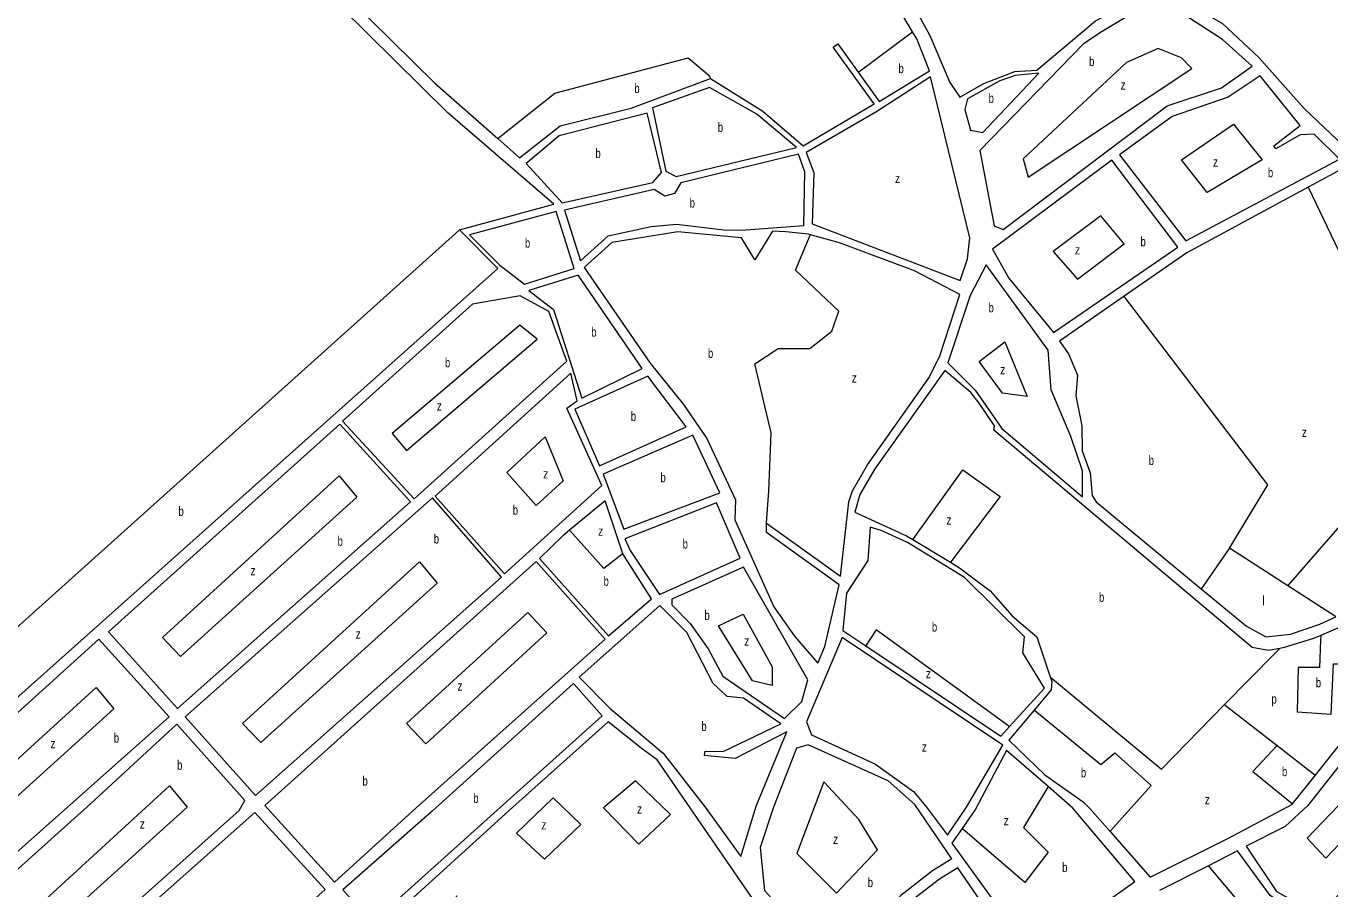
# Model space of a CAD drawing. Extents: x 639657 to 671642, y 222838 to 252123.
# Drawn here: x 645919 to 647301, y 229914 to 230829 of the extents above; entities that cross this region are included whole.
import ezdxf

# ---------------------------------------------------------------- set-up
doc = ezdxf.new("R2010")
doc.units = 0
doc.header["$LTSCALE"] = 4
doc.layers.add('1', color=7, linetype='Continuous', lineweight=13)
doc.layers.add('21', color=7, linetype='Continuous', lineweight=13)
doc.layers.add('7', color=7, linetype='Continuous')

msp = doc.modelspace()

# ---------------------------------------------------------------- linework, layer by layer
at = {"layer": '1'}
for p, q in [((646352.11, 230768.6), (646418.897, 230709.804)), ((646532.759, 230325.888), (646495.093, 230294.464)), ((646925.51, 229998.75), (646911.318, 229978.511)), ((647046.81, 229999.51), (647068.059, 229975.341))]:
    msp.add_line(p, q, dxfattribs=at)
for points in [[(646484.8, 231076.85), (646487.37, 231097.94), (646593.98, 231193.6), (646489.25, 231341.24), (646476.71, 231348.42), (646461.49, 231345.04), (646106.5, 231111.23), (646232.02, 230887.3), (646260.731, 230858.921), (646352.11, 230768.6)], [(646378.26, 230612.84), (646478.3, 230640.08), (646366.2, 230736.72), (646223.74, 230877.97), (646098.63, 231103.63), (645307.38, 230579.87)], [(646755.512, 231015.865), (646765.29, 231007.31), (646777.26, 230992.6), (646814.88, 230930.44), (646837.21, 230891.55), (646839.54, 230895.23), (646841.31, 230889.88), (646838.96, 230888.78), (646876.87, 230819.1), (646898.24, 230769.24), (646908.72, 230753.45), (646934.13, 230768.11), (646967.3, 230780.91), (646990.49, 230782.22), (647052.67, 230834.45), (647091.34, 230854.62), (647119.65, 230859.64), (647086.48, 230927.22), (647043.96, 230965.68), (647001.04, 231021.76), (646997.262, 231027.37)], [(646801.076, 230780.211), (646823.48, 230748.92), (646876.84, 230781.49), (646863.16, 230815.31), (646858.611, 230823.014), (646759.357, 230991.083)], [(646644.46, 230773.52), (646700.05, 230738.84), (646742.76, 230702.1), (646817.92, 230746.5), (646774.52, 230806.45), (646779.64, 230810.15), (646801.076, 230780.211)], [(646418.897, 230709.804), (646442.12, 230689.36), (646484.94, 230723.11), (646560.37, 230741.93), (646644.46, 230773.52)], [(647392.16, 230197.41), (647423.87, 230225.68), (647410.6, 230241.45), (647417.04, 230262.79), (647448.84, 230323.95), (647467.17, 230338.11), (647428.13, 230393.81), (647420.44, 230410.49), (647414.62, 230453.21), (647421.06, 230494.54), (647419.31, 230518.17), (647414.97, 230542.2), (647405.09, 230562.73), (647318.78, 230680.06), (647278.148, 230658.148)], [(647278.148, 230658.148), (647149.37, 230588.7), (647082.994, 230542.613)], [(645699.51, 230001.83), (645730.15, 229955.63), (645778.98, 230000.9), (646419.09, 230572), (646378.26, 230612.84)], [(646750.393, 230607.657), (646748.27, 230608.23), (646724.18, 230611), (646710.21, 230611.71), (646691.41, 230581.22), (646677.2, 230604.5), (646609.89, 230610.69), (646539.96, 230599.66), (646510.6, 230572.93), (646580.42, 230471.55), (646615.69, 230427.85), (646640.56, 230391.78), (646670.9, 230326.76), (646670.26, 230305.69), (646711.62, 230213.26), (646733.64, 230182.32)], [(646703.81, 230301.95), (646782.17, 230246), (646791.23, 230324.76), (646795.19, 230336.19), (646810.79, 230363.86), (646876.2, 230456.51), (646887.56, 230479.41), (646909, 230544.54), (646860.61, 230569.62), (646781.24, 230599.33), (646750.393, 230607.657)], [(647082.994, 230542.613), (647014.58, 230495.11), (647023.96, 230481.66), (647033.44, 230458.98), (647031.73, 230437.04), (647038.3, 230405.08), (647038.37, 230378.64), (647046.99, 230355.52), (647049.17, 230331.47), (647053.33, 230324.63), (647164.812, 230232.354)], [(647247.995, 230169.347), (647236.07, 230167.23), (647218.86, 230170.28), (646944.9, 230400.47), (646945.71, 230405.21), (646929.34, 230429.11), (646920.41, 230440.63), (646892.88, 230463.99), (646818.57, 230359.64), (646802.74, 230332.61), (646797.36, 230313.64), (646852.4, 230288.63), (646859.069, 230284.602), (646898.821, 230260.596)], [(646495.093, 230294.464), (646488.04, 230288.58), (646463.16, 230264.69), (646536.42, 230182.69), (646581.98, 230221.83), (646551.4, 230269.67), (646532.759, 230325.888)], [(646733.64, 230182.32), (646758.22, 230153.56), (646765.77, 230171.26), (646780.98, 230236.75), (646703.7, 230292.27), (646703.81, 230301.95)], [(646825.49, 230294.37), (646813.85, 230297.91), (646811.21, 230262.63), (646788.59, 230228.01), (646784.71, 230188.43), (646809.117, 230172.105)], [(646961.395, 230086.557), (646998.46, 230127.2), (646975.73, 230164.58), (646977.48, 230181.58), (646913.66, 230244.55), (646853.34, 230281.55), (646825.49, 230294.37)], [(646898.821, 230260.596), (646908.4, 230254.81), (646941.1, 230230.43), (646964.15, 230203.8), (646990.37, 230181.71), (647004.712, 230139.007), (647006.34, 230134.16)], [(647164.812, 230232.354), (647212.61, 230192.79), (647233.13, 230181.6), (647259.53, 230184.45), (647290.57, 230195.08), (647307.563, 230202.823)], [(647285.839, 230035.07), (647319.5, 230077.38), (647378.34, 230183.08), (647374.59, 230192.29), (647352.99, 230204.11), (647337.74, 230203.09), (647327.424, 230198.624), (647291.418, 230183.037)], [(647291.418, 230183.037), (647283.85, 230179.76), (647252.8, 230170.2), (647247.995, 230169.347)], [(646809.117, 230172.105), (646952.16, 230076.43), (646961.395, 230086.557)], [(647006.34, 230134.16), (647005.78, 230125.34), (646987.763, 230103.978)], [(647447.177, 230043.946), (647362.14, 230129.83), (647333.05, 230075.8), (647330.33, 230069.54), (647277.75, 230002.84)], [(646987.763, 230103.978), (646960.8, 230072.01), (646998.78, 230035.21), (647039.46, 230006.82), (647046.81, 229999.51)], [(646572.48, 230062.48), (646536.09, 230091.35), (646435.02, 230001.02)], [(646767.742, 229817.124), (646688.86, 229904.36), (646588.07, 230051.04), (646572.48, 230062.48)], [(646900.437, 229946.163), (646861, 230003.75), (646832.78, 230028.8), (646747.95, 230067.06), (646735.53, 230063.49), (646711.38, 230001.02)], [(647002.498, 230022.756), (646958.33, 230061.24), (646925.51, 229998.75)], [(647277.75, 230002.84), (647253.93, 229980.38), (647212.54, 229959.77), (647244.66, 229911.71), (647289.1, 229886.83), (647447.177, 230043.946)], [(647192.85, 229967.84), (647261.4, 230004.35), (647261.555, 230004.545), (647285.839, 230035.07)], [(646911.318, 229978.511), (646900.35, 229962.87), (646956.79, 229884.9), (646973.19, 229839.18), (646997.39, 229844.71), (647068.72, 229903.83), (647094.45, 229922.27), (647028.49, 230000.11), (647002.498, 230022.756)], [(646435.02, 230001.02), (646291.47, 229870.62), (646327.34, 229831.43), (646345.78, 229848.27), (646375.943, 229907.208)], [(646711.38, 230001.02), (646697.05, 229958.42), (646701.85, 229912.51), (646774.922, 229832.487)], [(647068.059, 229975.341), (647110.72, 229926.82), (647192.85, 229967.84)], [(647301.117, 229864.83), (647237.84, 229907.31), (647203.16, 229954.68), (647172.346, 229938.966), (647120.61, 229912.58)], [(646900.437, 229946.163), (646879.78, 229933.446), (646846.318, 229907.407), (646819.052, 229881.368), (646774.922, 229832.487)], [(646906.824, 229936.837), (646887.217, 229924.766), (646853.755, 229898.727), (646826.489, 229872.688), (646791.787, 229834.25), (646783.458, 229823.139)], [(646783.458, 229823.139), (646836.1, 229765.49), (646946.22, 229845.63), (646951.17, 229858.82), (646943.27, 229883.62), (646906.824, 229936.837)]]:
    msp.add_lwpolyline(points, dxfattribs=at)
for points in [[(647322.92, 230694.94), (647450.69, 230760.95), (647421.47, 230802.35), (647412.14, 230810.2), (647318.91, 230849.65), (647281.51, 230871.62), (647267.87, 230882.01), (647158.45, 231008.56), (647146.93, 231001.13), (647131.56, 230971.31), (647093.24, 230938.68), (647126.72, 230861.64), (647143.54, 230855.15), (647149.56, 230855.22), (647154.38, 230866.44), (647145.25, 230896.22), (647163.49, 230898.99), (647171, 230879.29), (647158.16, 230854.44), (647164.06, 230845.26), (647187.41, 230831.53), (647225.81, 230795.82), (647274.08, 230741.51)], [(647186.2, 230763.39), (647218.82, 230786.29), (647187.37, 230814.77), (647142.59, 230843.75), (647124.08, 230847.22), (647107.33, 230846.4), (647084.64, 230838), (647059.66, 230823.34), (647040.04, 230810.03), (646930.16, 230697.14), (646945.4, 230617.34), (646954.68, 230613.35), (647128.82, 230744.53)], [(646933.18, 230716.08), (646992.45, 230779.02), (646967.35, 230776.4), (646951.29, 230771.08), (646917.12, 230751.81), (646914.02, 230740.6), (646920.26, 230718.75)], [(647148.38, 230601.37), (647311.39, 230687.94), (647284.68, 230714.53), (647269.65, 230713.52), (647244.03, 230698.85), (647241.63, 230702.05), (647269.76, 230723.62), (647227.31, 230776.27), (647193.17, 230753.57), (647134.1, 230732.97), (647078.23, 230692.64)], [(646643.49, 230763.84), (646583.14, 230742.16), (646597.17, 230675.04), (646607.97, 230669.56), (646735.69, 230700.09), (646693.64, 230735.55)], [(646919.54, 230604.61), (646877.77, 230775.05), (646819.73, 230737.7), (646746.06, 230695.04), (646754.02, 230673.84), (646752.24, 230619.45), (646909.28, 230559.37), (646916.98, 230582.23)], [(646583.33, 230663.29), (646592.67, 230673.7), (646577.39, 230736.73), (646483.98, 230712.57), (646449.06, 230683.2), (646487.1, 230641.46)], [(646744.34, 230674.6), (646737.7, 230693.23), (646613.2, 230662.73), (646606.23, 230651.49), (646596.16, 230648.59), (646584.92, 230655.78), (646489.54, 230633.96), (646506.66, 230579.98), (646535.81, 230606.71), (646581.47, 230616.42), (646608.51, 230619.06), (646658.63, 230613.12), (646677.33, 230612.67), (646743.45, 230617.64)], [(647008.25, 230504.29), (647140.07, 230594.62), (647070.13, 230686.97), (646943.3, 230592.6), (646960.81, 230561.83)], [(646499.87, 230571.96), (646480.75, 230632.58), (646389.06, 230607.58), (646420.98, 230575.67), (646447.19, 230555.52)], [(647002.44, 230485.53), (646936.6, 230575.98), (646919.76, 230543.36), (646896.02, 230471.97), (646925.11, 230443.04), (646953.25, 230402.49), (647038.88, 230329.86), (647038.8, 230357.37), (647026.6, 230393.78), (647005.67, 230443.43)], [(646572.11, 230465.88), (646504.03, 230564.91), (646451.99, 230548.69), (646477.99, 230528.54), (646508.2, 230434.5)], [(646330.37, 230327.82), (646492.1, 230473.88), (646473.06, 230526.55), (646442.6, 230543.01), (646392.2, 230534.11), (646254.3, 230410.21)], [(646503.29, 230431.87), (646496.32, 230461.03), (646352.46, 230330.83), (646426.16, 230248.41), (646529.16, 230341.87), (646492.2, 230423.8)], [(646618.74, 230404.03), (646578.2, 230457.99), (646500.59, 230422.81), (646526.79, 230362.69)], [(646326.53, 230324.55), (646251.54, 230406.96), (646006.38, 230186.79), (646079.2, 230105.64)], [(646654.27, 230334.33), (646625.7, 230395.29), (646530.53, 230354.13), (646552.42, 230295.68)], [(646422.98, 230244.72), (646349.69, 230328.87), (646087.67, 230096.92), (646162.24, 230013.21)], [(646675.84, 230264.91), (646650.95, 230323.76), (646553.6, 230285.59), (646559.32, 230272.97), (646590.31, 230226.43)], [(646172.1, 230002.84), (646245.75, 229921.47), (646332.38, 230000.17), (646532.81, 230179), (646459.54, 230261.43)], [(646747.66, 230136.04), (646679.6, 230255.28), (646603.47, 230221.41), (646603.32, 230215.39), (646623.08, 230195.82), (646642.05, 230168.93), (646657.61, 230139.86), (646722.96, 230094.96), (646741.46, 230112.98)], [(646638.7, 230001.02), (646676.57, 229948.64), (646692.76, 230001.93), (646725.47, 230080.8), (646670.55, 230052.73), (646638.08, 230055.63), (646638.89, 230060.36), (646658.01, 230059.91), (646718.93, 230089.33), (646679.55, 230116.44), (646662.13, 230118.2), (646647.37, 230132.23), (646619.52, 230186.32), (646590.87, 230214.83), (646505.3, 230138.74), (646538.31, 230105.12), (646594.44, 230058.41)], [(645797.39, 229999.45), (645737.19, 229945), (645803.46, 229859.66), (646070.49, 230096.75), (645995.93, 230179.16)], [(646872.42, 230002.31), (646895.92, 229971.18), (646915.97, 230001.02), (646954.41, 230066.79), (646783.93, 230180.68), (646746.19, 230091.54), (646751.49, 230077.62), (646819.27, 230046.72), (646859.75, 230017.47)], [(646349.22, 229996.66), (646254.7, 229913.23), (646285.76, 229878.91), (646529.58, 230097.73), (646499.35, 230132.24)], [(645986.99, 230004.65), (645813.09, 229848.86), (645886.82, 229767.29), (646144.6, 229997.51), (646150.69, 230007.94), (646078.52, 230088.87)], [(646161.41, 229995.34), (645895.33, 229759.04), (645969.95, 229675.77), (646235.99, 229913.58)]]:
    msp.add_lwpolyline(points, close=True, dxfattribs=at)
at = {"layer": '21'}
for points in [[(646801.076, 230780.211), (646801.576, 230780.583), (646858.611, 230823.014)], [(646418.897, 230709.804), (646419.397, 230710.202), (646479.466, 230758.007), (646620.753, 230795.205), (646643.062, 230776.606), (646644.233, 230774.02), (646644.46, 230773.52)], [(647278.148, 230658.148), (647278.387, 230657.648), (647309.839, 230591.855), (647354.456, 230541.017), (647316.035, 230514.978), (647339.583, 230479.02), (647373.046, 230507.539), (647395.354, 230472.82), (647358.174, 230445.542), (647397.833, 230400.904), (647375.525, 230381.065), (647405.269, 230342.627), (647386.679, 230327.747), (647371.807, 230315.348), (647360.652, 230304.188), (647387.918, 230269.47), (647373.046, 230255.831), (647325.95, 230315.348), (647257.032, 230236.183), (647256.597, 230235.683)], [(646378.26, 230612.84), (646377.76, 230612.391), (645768.61, 230065.789), (645768.11, 230065.34)], [(646703.81, 230301.95), (646703.846, 230302.45), (646706.27, 230335.807), (646708.749, 230397.804), (646691.398, 230470.961), (646716.185, 230487.08), (646749.648, 230487.08), (646773.196, 230505.679), (646780.632, 230526.758), (646734.775, 230570.156), (646750.185, 230607.157), (646750.393, 230607.657)], [(647194.578, 230275.669), (647235.477, 230342.626), (647083.375, 230542.113), (647082.994, 230542.613)], [(646859.069, 230284.602), (646859.426, 230285.103), (646912.004, 230358.745), (646951.663, 230330.227), (646899.199, 230261.095), (646898.821, 230260.596)], [(646551.4, 230269.67), (646550.9, 230269.275), (646531.52, 230253.971), (646495.543, 230293.964), (646495.093, 230294.464)], [(647194.578, 230275.669), (647194.234, 230275.169), (647165.156, 230232.854), (647164.812, 230232.354)], [(647307.563, 230202.823), (647307.063, 230203.145), (647256.597, 230235.683), (647194.578, 230275.669)], [(647291.418, 230183.037), (647291.21, 230178.036), (647290.009, 230149.195), (647267.701, 230149.195), (647266.461, 230102.078), (647302.403, 230099.598), (647304.881, 230152.915), (647325.951, 230152.915), (647327.408, 230198.124), (647327.424, 230198.624)], [(646961.395, 230086.557), (646960.895, 230086.92), (646820.291, 230188.873), (646809.45, 230172.605), (646809.117, 230172.105)], [(647189.585, 230109.666), (647243.101, 230164.347), (647247.995, 230169.347)], [(647004.712, 230139.007), (647005.212, 230138.593), (647122.695, 230041.321), (647189.585, 230109.666)], [(646987.763, 230103.978), (646988.263, 230103.569), (647058.248, 230046.28), (647073.121, 230058.68), (647111.541, 230023.961), (647068.506, 229975.841), (647068.059, 229975.341)], [(647189.585, 230109.666), (647190.085, 230109.279), (647245.342, 230066.455)], [(647245.342, 230066.455), (647244.872, 230065.955), (647219.365, 230038.841), (647261.055, 230004.951), (647261.555, 230004.545)], [(647245.342, 230066.455), (647285.339, 230035.457), (647285.839, 230035.07)], [(647002.498, 230022.756), (647002.198, 230022.256), (646976.451, 229979.323), (647002.477, 229953.285), (646977.69, 229921.046), (646911.818, 229978.078), (646911.318, 229978.511)], [(647301.117, 229864.83), (647300.675, 229864.33), (647274.004, 229834.166), (647260.419, 229840.439), (647238.474, 229823.711), (647200.854, 229867.622), (647223.844, 229878.077), (647172.77, 229938.465), (647172.346, 229938.966)]]:
    msp.add_lwpolyline(points, dxfattribs=at)
for points in [[(646976.091, 230688.235), (646981.408, 230668.731), (647154.918, 230784.046), (647143.764, 230795.205), (647118.977, 230805.125), (647085.514, 230790.245)], [(647199.03, 230725.161), (647229.28, 230687.33), (647171.03, 230652.612), (647143.764, 230687.33)], [(647007.926, 230590.053), (647033.461, 230560.856), (647083.035, 230598.054), (647058.248, 230627.813)], [(646307.03, 230396.985), (646322.068, 230379.205), (646460.877, 230496.999), (646442.286, 230511.879)], [(646956.666, 230494.336), (646980.169, 230436.242), (646954.142, 230439.962), (646929.355, 230473.441)], [(646469.232, 230393.538), (646488.142, 230346.967), (646459.637, 230320.928), (646428.653, 230355.646)], [(646250.754, 230352.206), (646269.523, 230329.671), (646082.537, 230160.582), (646063.358, 230180.968)], [(646335.857, 230261.066), (646354.626, 230238.531), (646167.64, 230069.442), (646148.461, 230089.828)], [(646450.914, 230207.184), (646470.894, 230185.765), (646342.641, 230068.242), (646322.264, 230089.828)], [(646652.855, 230193.221), (646679.004, 230205.613), (646709.988, 230149.816), (646709.988, 230129.977), (646688.919, 230134.937)], [(645993.048, 230127.953), (646011.817, 230105.418), (645824.831, 229936.329), (645805.652, 229956.715)], [(647360.544, 230054.959), (647380.595, 230034.9), (647296.994, 229947.079), (647277.139, 229967.989)], [(646070.959, 230023.621), (646089.728, 230001.086), (645902.742, 229831.997), (645883.563, 229852.383)], [(646565.048, 230028.963), (646531.009, 230000.4), (646568.629, 229961.717), (646602.069, 229993.081)], [(646764.483, 230027.996), (646736.015, 229952.045), (646778.153, 229909.887), (646821.53, 229955.765), (646801.701, 229988.003)], [(646438.856, 229973.319), (646468.309, 229946.034), (646506.974, 229982.626), (646477.714, 230010.855)]]:
    msp.add_lwpolyline(points, close=True, dxfattribs=at)

# ---------------------------------------------------------------- texts
at = {"layer": '7'}
for s, width, p in [('b', 0.75, (646843.838, 230779.086)), ('b', 0.75, (647045.855, 230786.525)), ('b', 0.75, (646563.742, 230758.007)), ('z', 0.8, (647079.317, 230761.727)), ('b', 0.75, (646939.378, 230747.55)), ('b', 0.75, (646652.228, 230716.7)), ('b', 0.75, (646522.503, 230689.095)), ('z', 0.8, (647177.227, 230679.891)), ('b', 0.75, (647235.477, 230668.731)), ('z', 0.8, (646840.12, 230662.532)), ('b', 0.75, (646622.424, 230636.605)), ('b', 0.75, (646447.748, 230594.05)), ('b', 0.75, (647100.386, 230595.575)), ('z', 0.8, (647030.982, 230586.895)), ('b', 0.75, (646939.27, 230525.518)), ('b', 0.75, (646518.055, 230499.705)), ('b', 0.75, (646641.823, 230477.16)), ('b', 0.75, (646362.967, 230467.241)), ('z', 0.8, (646794.265, 230451.122)), ('z', 0.8, (646951.664, 230459.801)), ('z', 0.8, (646354.291, 230421.363)), ('b', 0.75, (646560.012, 230410.34)), ('z', 0.8, (647271.418, 230393.464)), ('b', 0.75, (647109.062, 230363.706)), ('z', 0.8, (646467.073, 230349.446)), ('b', 0.75, (646591.405, 230345.485)), ('b', 0.75, (646080.393, 230309.768)), ('b', 0.75, (646434.85, 230311.008)), ('z', 0.8, (646894.653, 230300.469)), ('z', 0.8, (646525.323, 230288.689)), ('b', 0.75, (646249.147, 230278.105)), ('b', 0.75, (646351.031, 230280.503)), ('b', 0.75, (646614.945, 230275.095)), ('z', 0.8, (646156.852, 230246.925)), ('b', 0.75, (646531.137, 230235.635)), ('b', 0.75, (647056.387, 230218.56)), ('b', 0.75, (646638.105, 230199.414)), ('b', 0.75, (646879.204, 230187.17)), ('z', 0.8, (646268.325, 230179.769)), ('z', 0.8, (646680.243, 230172.135)), ('z', 0.8, (646872.85, 230137.708)), ('z', 0.8, (646376.202, 230124.606)), ('b', 0.75, (647286.291, 230128.117)), ('p', 0.75, (647239.195, 230110.758)), ('b', 0.75, (646634.807, 230081.735)), ('z', 0.8, (645944.694, 230063.445)), ('b', 0.75, (646011.817, 230069.442)), ('z', 0.8, (646868.626, 230059.92)), ('b', 0.75, (646078.941, 230040.66)), ('b', 0.75, (647037.179, 230032.641)), ('b', 0.75, (647250.349, 230033.881)), ('b', 0.75, (646275.517, 230023.871)), ('b', 0.75, (646392.994, 230005.575)), ('z', 0.8, (646566.541, 229994.127)), ('z', 0.8, (647168.551, 230004.123)), ('z', 0.8, (646955.381, 229981.804)), ('z', 0.8, (646039.386, 229978.301)), ('z', 0.8, (646465.175, 229977.399)), ('z', 0.8, (646774.434, 229961.965)), ('b', 0.75, (647017.349, 229932.206)), ('b', 0.75, (646811.181, 229916.275))]:
    msp.add_text(s, height=10, dxfattribs=dict(at, width=width)).set_placement(p)
msp.add_text('l', height=10, dxfattribs=at).set_placement((647229.28, 230214.913))

doc.saveas('drawing.dxf')
